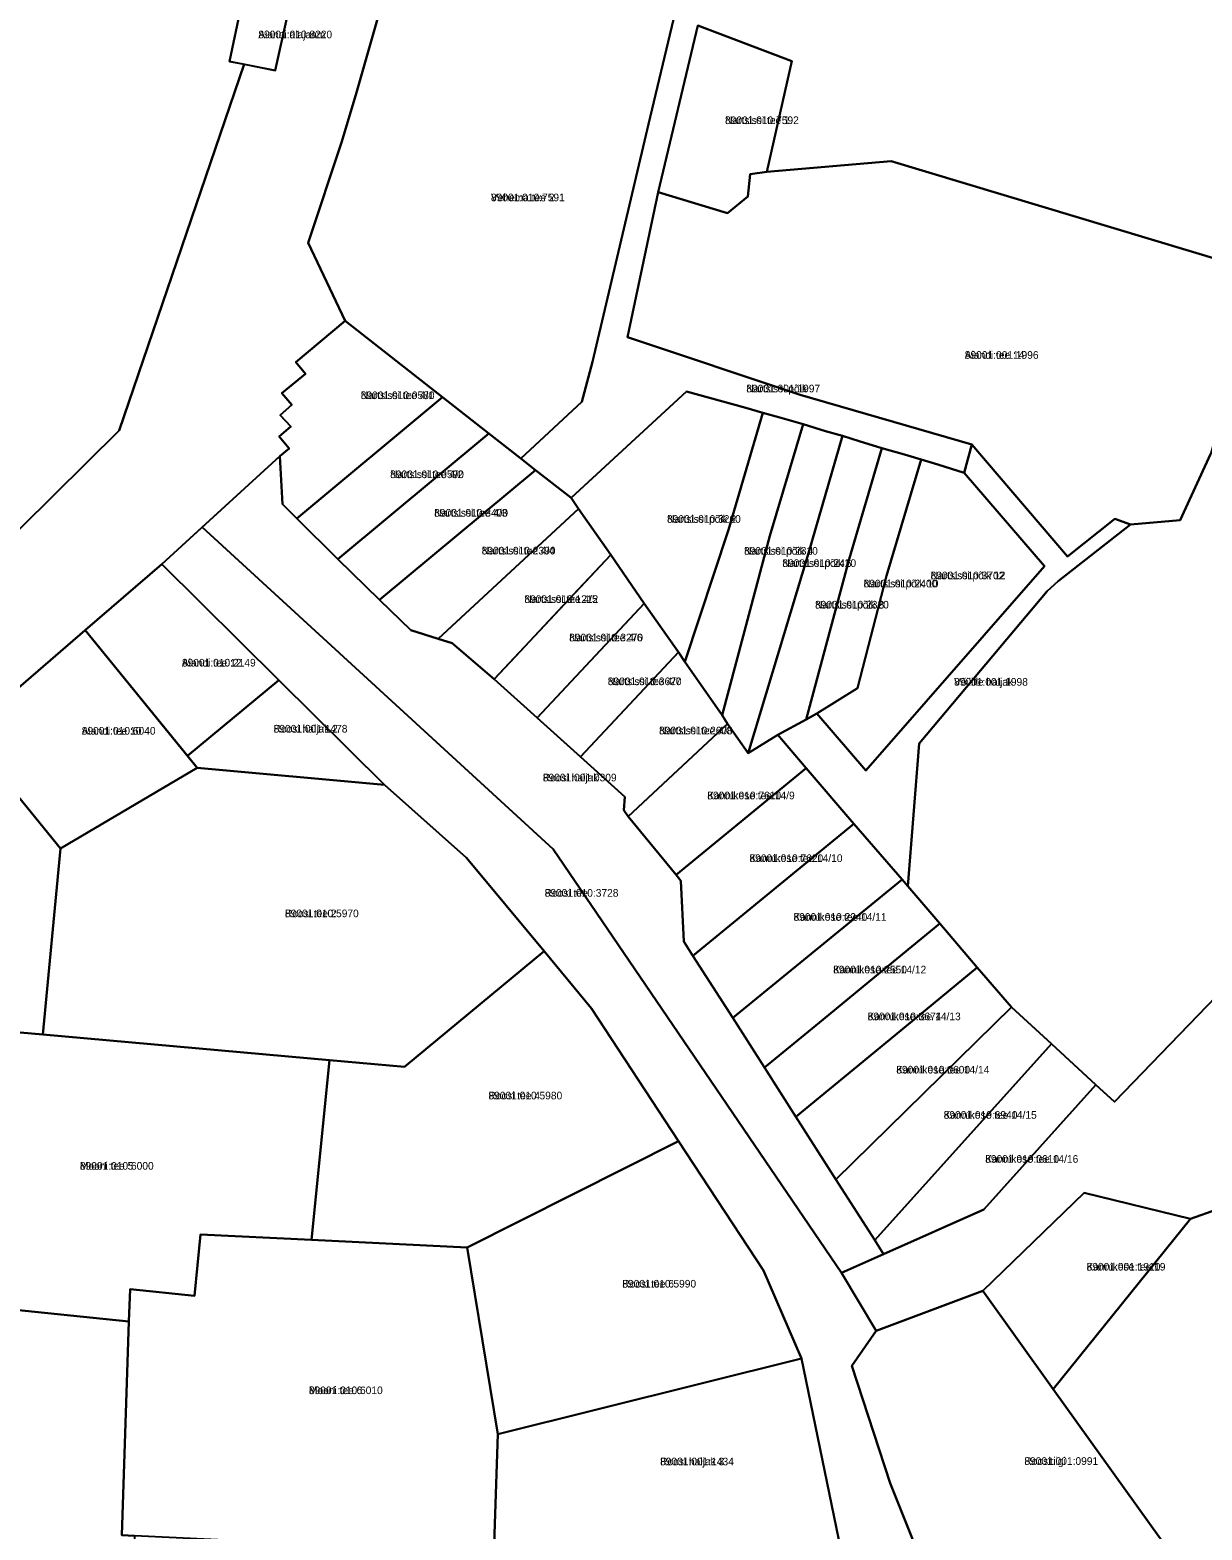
# Model space of a CAD drawing. Extents: x 526849 to 562296, y 6591741 to 6618546.
# Drawn here: x 547477.1 to 547707.4, y 6596107.7 to 6596402.5 of the extents above; entities that cross this region are included whole.
import ezdxf

# ---------------------------------------------------------------- set-up
doc = ezdxf.new("R2010")
doc.units = 0
for name, color, linetype in [('L_AADRESS', 7, 'Continuous'), ('PIIR', 7, 'Continuous'), ('TUNNUS', 7, 'Continuous')]:
    doc.layers.add(name, color=color, linetype=linetype)

msp = doc.modelspace()

# ---------------------------------------------------------------- linework, layer by layer
at = {"layer": 'PIIR'}
for points in [[(547547.94, 6596413.68), (547541.27, 6596390.17), (547538.35, 6596380.55), (547531.76, 6596360.64), (547539.03, 6596345.34), (547529.29, 6596337.2), (547531.22, 6596334.92), (547526.57, 6596331.13), (547528.5, 6596328.81), (547526.21, 6596326.8), (547528.35, 6596324.59), (547526.03, 6596322.59), (547527.98, 6596320.24), (547526.19, 6596318.74), (547502.97, 6596297.54), (547487.91, 6596284.53), (547464.56, 6596264.36)], [(547436.55, 6596266.41), (547494.58, 6596323.81), (547519.19, 6596395.74), (547525.25, 6596394.54), (547527.65, 6596405.37)], [(547608.34, 6596403.39), (547600.54, 6596370.65), (547594.52, 6596342.12), (547628.42, 6596330.79), (547662.19, 6596321.02), (547660.66, 6596315.49), (547655.5, 6596317.1), (547652.19, 6596318.08), (547648.91, 6596319.06), (547644.51, 6596320.34), (547640.02, 6596321.68), (547636.77, 6596322.72), (547633.4, 6596323.68), (547629.02, 6596325.01), (547624.43, 6596326.32), (547621.1, 6596327.29), (547617.74, 6596328.27), (547606.1, 6596331.43), (547583.42, 6596310.53), (547576.41, 6596316.01), (547573.51, 6596318.28), (547585.49, 6596329.44), (547587.59, 6596337.3), (547598.61, 6596384.01), (547603.56, 6596404.56)], [(547719.05, 6596354.82), (547646.28, 6596376.7), (547621.91, 6596374.59), (547626.79, 6596396.36), (547608.34, 6596403.39)], [(547706.39, 6596096.06), (547678.12, 6596135.41), (547705.14, 6596168.88), (547751.73, 6596185.38), (547765.81, 6596222.42), (547774.28, 6596244.68), (547784.51, 6596273.18), (547786.25, 6596291.35), (547816.28, 6596354.76), (547818.08, 6596359.67), (547851.56, 6596357.26), (547867.85, 6596356.78), (547882.68, 6596357.65), (547882.59, 6596354.87), (547879.67, 6596315.25), (547878.79, 6596293.54), (547877.89, 6596271.47), (547876.9, 6596247.63), (547875.48, 6596216.32), (547874.71, 6596199.06), (547874.51, 6596195.05), (547877.57, 6596194.93), (547877.34, 6596152.04), (547875.55, 6596092.04)], [(547763.12, 6596267.42), (547690.17, 6596191.87), (547686.52, 6596195.24), (547677.79, 6596203.24), (547669.94, 6596210.45), (547663.24, 6596218.29), (547655.88, 6596226.9), (547649.56, 6596234.23), (547651.83, 6596262.3), (547676.97, 6596292.19), (547679.13, 6596294.15), (547693.33, 6596305.3), (547703.1, 6596306.18), (547709.04, 6596319.15)], [(547751.73, 6596185.38), (547705.14, 6596168.88), (547684.21, 6596173.98), (547664.3, 6596154.73), (547643.38, 6596146.88), (547636.58, 6596158.24), (547644.82, 6596161.92), (547664.55, 6596170.73), (547686.52, 6596195.24), (547690.17, 6596191.87), (547763.12, 6596267.42)]]:
    msp.add_lwpolyline(points, dxfattribs=at)
for points in [[(547558.11, 6596330.34), (547539.03, 6596345.34), (547531.76, 6596360.64), (547538.35, 6596380.55), (547541.27, 6596390.17), (547547.94, 6596413.68), (547575.43, 6596415.26), (547586.41, 6596413.51), (547603.56, 6596404.56), (547598.61, 6596384.01), (547587.59, 6596337.3), (547585.49, 6596329.44), (547573.51, 6596318.28), (547567.22, 6596323.2)], [(547416.77, 6596407.3), (547432.18, 6596406.08), (547518.58, 6596407.17), (547516.26, 6596396.32), (547519.19, 6596395.74), (547494.58, 6596323.81), (547436.55, 6596266.41), (547362.32, 6596292.91), (547414.29, 6596397.55)], [(547527.65, 6596405.37), (547525.25, 6596394.54), (547516.26, 6596396.32), (547518.58, 6596407.17)], [(547626.79, 6596396.36), (547621.91, 6596374.59), (547618.63, 6596374.15), (547618.13, 6596369.78), (547614.13, 6596366.5), (547600.54, 6596370.65), (547608.34, 6596403.39)], [(547594.52, 6596342.12), (547600.54, 6596370.65), (547614.13, 6596366.5), (547618.13, 6596369.78), (547618.63, 6596374.15), (547621.91, 6596374.59), (547646.28, 6596376.7), (547719.05, 6596354.82), (547718.25, 6596351.97), (547715.23, 6596341.14), (547712.28, 6596330.22), (547709.13, 6596319.31), (547709.04, 6596319.15), (547703.1, 6596306.18), (547693.33, 6596305.3), (547690.25, 6596306.42), (547680.99, 6596299.05), (547662.19, 6596321.02), (547628.42, 6596330.79)], [(547526.7, 6596309.3), (547526.19, 6596318.74), (547527.98, 6596320.24), (547526.03, 6596322.59), (547528.35, 6596324.59), (547526.21, 6596326.8), (547528.5, 6596328.81), (547526.57, 6596331.13), (547531.22, 6596334.92), (547529.29, 6596337.2), (547539.03, 6596345.34), (547558.11, 6596330.34), (547529.52, 6596306.51)], [(547591.19, 6596299.37), (547584.89, 6596308.42), (547583.42, 6596310.53), (547606.1, 6596331.43), (547617.74, 6596328.27), (547621.1, 6596327.29), (547614.32, 6596304.24), (547605.77, 6596278.36), (547604.49, 6596280.2), (547597.79, 6596289.82)], [(547567.22, 6596323.2), (547537.58, 6596298.52), (547529.52, 6596306.51), (547558.11, 6596330.34)], [(547605.77, 6596278.36), (547614.32, 6596304.24), (547621.1, 6596327.29), (547624.43, 6596326.32), (547629.02, 6596325.01), (547622.47, 6596303.12), (547613.08, 6596267.85)], [(547573.51, 6596318.28), (547576.41, 6596316.01), (547545.79, 6596290.52), (547537.58, 6596298.52), (547567.22, 6596323.2)], [(547614.15, 6596266.15), (547613.08, 6596267.85), (547622.47, 6596303.12), (547629.02, 6596325.01), (547633.4, 6596323.68), (547636.77, 6596322.72), (547630.08, 6596299.69), (547618.19, 6596260.36)], [(547629.59, 6596267.02), (547624.02, 6596264.01), (547618.19, 6596260.36), (547630.08, 6596299.69), (547636.77, 6596322.72), (547640.02, 6596321.68), (547644.51, 6596320.34), (547638.05, 6596298.49)], [(547660.66, 6596315.49), (547662.19, 6596321.02), (547680.99, 6596299.05), (547690.25, 6596306.42), (547693.33, 6596305.3), (547679.13, 6596294.15), (547676.97, 6596292.19), (547651.83, 6596262.3), (547649.56, 6596234.23), (547648.47, 6596235.58), (547638.97, 6596246.52), (547629.63, 6596257.45), (547624.02, 6596264.01), (547629.59, 6596267.02), (547631.69, 6596268.16), (547641.32, 6596257.01), (547676.43, 6596297.15)], [(547629.59, 6596267.02), (547638.05, 6596298.49), (547644.51, 6596320.34), (547648.91, 6596319.06), (547652.19, 6596318.08), (547645.41, 6596295.21), (547639.68, 6596273.18), (547631.69, 6596268.16)], [(547636.58, 6596158.24), (547579.89, 6596241.49), (547510.9, 6596304.78), (547526.19, 6596318.74), (547526.7, 6596309.3), (547529.52, 6596306.51), (547537.58, 6596298.52), (547545.79, 6596290.52), (547551.91, 6596284.55), (547557.3, 6596282.85), (547560.03, 6596282.03), (547568.3, 6596274.91), (547576.76, 6596267.31), (547585.29, 6596259.64), (547594, 6596251.81), (547593.8, 6596249.16), (547594.63, 6596247.97), (547604.04, 6596236.48), (547604.98, 6596235.33), (547605.54, 6596223.35), (547607.32, 6596220.55), (547615.18, 6596208.37), (547621.42, 6596198.64), (547627.61, 6596188.92), (547635.47, 6596176.59), (547643.07, 6596164.66), (547644.82, 6596161.92)], [(547652.19, 6596318.08), (547655.5, 6596317.1), (547660.66, 6596315.49), (547676.43, 6596297.15), (547641.32, 6596257.01), (547631.69, 6596268.16), (547639.68, 6596273.18), (547645.41, 6596295.21)], [(547583.42, 6596310.53), (547584.89, 6596308.42), (547557.3, 6596282.85), (547551.91, 6596284.55), (547545.79, 6596290.52), (547576.41, 6596316.01)], [(547584.89, 6596308.42), (547591.19, 6596299.37), (547582.64, 6596290.24), (547572.5, 6596279.4), (547568.3, 6596274.91), (547560.03, 6596282.03), (547557.3, 6596282.85)], [(547502.97, 6596297.54), (547510.9, 6596304.78), (547579.89, 6596241.49), (547636.58, 6596158.24), (547643.38, 6596146.88), (547638.59, 6596140), (547646.1, 6596116.96), (547653.47, 6596098.6), (547644.16, 6596099.09), (547637.32, 6596099.45), (547628.66, 6596141.44), (547621.22, 6596158.7), (547604.53, 6596184.16), (547587.45, 6596210.21), (547578.09, 6596221.49), (547562.86, 6596239.84), (547546.73, 6596254.13), (547525.95, 6596274.75)], [(547568.3, 6596274.91), (547591.19, 6596299.37), (547597.79, 6596289.82), (547576.76, 6596267.31)], [(547502.97, 6596297.54), (547525.95, 6596274.75), (547508.05, 6596259.84), (547487.91, 6596284.53)], [(547576.76, 6596267.31), (547597.79, 6596289.82), (547604.49, 6596280.2), (547585.29, 6596259.64)], [(547509.93, 6596257.53), (547483.08, 6596241.65), (547464.56, 6596264.36), (547487.91, 6596284.53)], [(547605.77, 6596278.36), (547613.08, 6596267.85), (547614.15, 6596266.15), (547594.63, 6596247.97), (547593.8, 6596249.16), (547594, 6596251.81), (547585.29, 6596259.64), (547604.49, 6596280.2)], [(547508.05, 6596259.84), (547525.95, 6596274.75), (547546.73, 6596254.13), (547509.93, 6596257.53)], [(547618.19, 6596260.36), (547624.02, 6596264.01), (547629.63, 6596257.45), (547604.04, 6596236.48), (547594.63, 6596247.97), (547614.15, 6596266.15)], [(547464.56, 6596264.36), (547483.08, 6596241.65), (547479.59, 6596205.09), (547465.46, 6596206.34), (547437.32, 6596240.84)], [(547562.86, 6596239.84), (547578.09, 6596221.49), (547550.7, 6596198.77), (547535.96, 6596200.08), (547479.59, 6596205.09), (547483.08, 6596241.65), (547509.93, 6596257.53), (547546.73, 6596254.13)], [(547605.54, 6596223.35), (547604.98, 6596235.33), (547604.04, 6596236.48), (547629.63, 6596257.45), (547638.97, 6596246.52), (547607.32, 6596220.55)], [(547638.97, 6596246.52), (547648.47, 6596235.58), (547615.18, 6596208.37), (547607.32, 6596220.55)], [(547615.18, 6596208.37), (547648.47, 6596235.58), (547649.56, 6596234.23), (547655.88, 6596226.9), (547641.94, 6596215.47), (547632.92, 6596208.07), (547621.42, 6596198.64)], [(547621.42, 6596198.64), (547632.92, 6596208.07), (547641.94, 6596215.47), (547655.88, 6596226.9), (547663.24, 6596218.29), (547650.43, 6596207.73), (547638.97, 6596198.29), (547627.61, 6596188.92)], [(547532.41, 6596164.75), (547535.96, 6596200.08), (547550.7, 6596198.77), (547578.09, 6596221.49), (547587.45, 6596210.21), (547604.53, 6596184.16), (547563.01, 6596163.24)], [(547635.47, 6596176.59), (547627.61, 6596188.92), (547638.97, 6596198.29), (547650.43, 6596207.73), (547663.24, 6596218.29), (547669.94, 6596210.45)], [(547635.47, 6596176.59), (547669.94, 6596210.45), (547677.79, 6596203.24), (547643.07, 6596164.66)], [(547437.6, 6596154.79), (547440.01, 6596178.32), (547438.61, 6596184.25), (547438.73, 6596191.13), (547442.64, 6596200.1), (547442.55, 6596208.38), (547465.46, 6596206.34), (547479.59, 6596205.09), (547535.96, 6596200.08), (547532.41, 6596164.75), (547510.61, 6596165.82), (547509.4, 6596153.78), (547496.75, 6596155.08), (547496.53, 6596148.71), (547445.48, 6596153.98)], [(547686.52, 6596195.24), (547664.55, 6596170.73), (547644.82, 6596161.92), (547643.07, 6596164.66), (547677.79, 6596203.24)], [(547563.01, 6596163.24), (547604.53, 6596184.16), (547621.22, 6596158.7), (547628.66, 6596141.44), (547569.02, 6596126.6)], [(547678.12, 6596135.41), (547664.3, 6596154.73), (547684.21, 6596173.98), (547705.14, 6596168.88)], [(547496.53, 6596148.71), (547496.75, 6596155.08), (547509.4, 6596153.78), (547510.61, 6596165.82), (547532.41, 6596164.75), (547563.01, 6596163.24), (547569.02, 6596126.6), (547568.22, 6596103.06), (547563.12, 6596103.32), (547546.75, 6596104.11), (547530.38, 6596104.94), (547513.97, 6596105.78), (547497.6, 6596106.6), (547495.1, 6596106.73)], [(547664.3, 6596154.73), (547678.12, 6596135.41), (547706.39, 6596096.06), (547688.29, 6596096.92), (547675.94, 6596097.66), (547660.04, 6596098.26), (547653.47, 6596098.6), (547646.1, 6596116.96), (547638.59, 6596140), (547643.38, 6596146.88)], [(547270.52, 6596117.43), (547316.37, 6596071.96), (547361.8, 6596108.26), (547443.86, 6596105.58), (547445.48, 6596153.98), (547496.53, 6596148.71), (547495.1, 6596106.73), (547497.6, 6596106.6), (547497.04, 6596090.99), (547492.97, 6596090.65), (547490.86, 6596041.33), (547490.66, 6596035.68), (547488.51, 6595983.56), (547492.72, 6595983.52), (547492.6, 6595979.92), (547491.98, 6595964.43), (547491.76, 6595958.44), (547232.4, 6596069.31), (547228.78, 6596080.54)], [(547628.66, 6596141.44), (547637.32, 6596099.45), (547628.31, 6596099.92), (547612.01, 6596100.77), (547595.64, 6596101.63), (547579.51, 6596102.47), (547568.22, 6596103.06), (547569.02, 6596126.6)]]:
    msp.add_lwpolyline(points, close=True, dxfattribs=at)

# ---------------------------------------------------------------- texts
at = {"layer": 'L_AADRESS'}
for s, p in [('Aiandi alajaam', (547521.95, 6596400.85)), ('Nartsissi tee 1', (547613.66, 6596384)), ('Vehema tee 2', (547567.66, 6596368.83)), ('Aiandi tee 14', (547660.78, 6596337.88)), ('Nartsissi tee 4/1', (547542.07, 6596329.96)), ('Nartsissi põik', (547617.85, 6596331.28)), ('Nartsissi tee 4/2', (547547.85, 6596314.43)), ('Nartsissi tee 4/3', (547556.51, 6596306.86)), ('Nartsissi põik 2', (547602.26, 6596305.65)), ('Nartsissi tee 4/4', (547565.84, 6596299.43)), ('Nartsissi põik 4', (547617.4, 6596299.38)), ('Nartsissi põik 6', (547624.93, 6596296.98)), ('Nartsissi põik 12', (547654.06, 6596294.55)), ('Nartsissi põik 10', (547640.89, 6596292.96)), ('Nartsissi tee 4/5', (547574.24, 6596289.91)), ('Nartsissi põik 8', (547631.35, 6596288.81)), ('Nartsissi tee 4/6', (547583.04, 6596282.35)), ('Aiandi tee 12', (547506.93, 6596277.41)), ('Nartsissi tee 4/7', (547590.62, 6596273.75)), ('Võilille haljak', (547658.68, 6596273.64)), ('Aiandi tee 10', (547487.25, 6596264.03)), ('Roosi haljak 2', (547524.96, 6596264.44)), ('Nartsissi tee 4/8', (547600.69, 6596264.08)), ('Roosi haljak', (547577.86, 6596254.84)), ('Kannikese tee 14/9', (547610.18, 6596251.32)), ('Kannikese tee 14/10', (547618.46, 6596239)), ('Roosi tee', (547578.22, 6596232.18)), ('Roosi tee 2', (547527.18, 6596228.15)), ('Kannikese tee 14/11', (547627.12, 6596227.45)), ('Kannikese tee 14/12', (547634.91, 6596217.11)), ('Kannikese tee 14/13', (547641.69, 6596207.91)), ('Kannikese tee 14/14', (547647.32, 6596197.44)), ('Roosi tee 4', (547567.17, 6596192.36)), ('Kannikese tee 14/15', (547656.63, 6596188.55)), ('Kannikese tee 14/16', (547664.8, 6596179.9)), ('Mooni tee 5', (547486.88, 6596178.54)), ('Kannikese tee 19', (547684.72, 6596158.72)), ('Roosi tee 6', (547593.48, 6596155.38)), ('Mooni tee 6', (547531.89, 6596134.44)), ('Roosi haljak 3', (547600.9, 6596120.45)), ('Roositiigi', (547672.49, 6596120.54))]:
    msp.add_text(s, height=1.5, dxfattribs=at).set_placement(p)
at = {"layer": 'TUNNUS'}
for s, p in [('89001:010:8220', (547521.95, 6596400.85)), ('89001:010:7592', (547613.66, 6596384)), ('89001:010:7591', (547567.66, 6596368.83)), ('89001:001:1996', (547660.78, 6596337.88)), ('89001:010:0580', (547542.07, 6596329.96)), ('89001:001:1997', (547617.85, 6596331.28)), ('89001:010:0590', (547547.85, 6596314.43)), ('89001:010:8400', (547556.51, 6596306.86)), ('89001:010:3260', (547602.26, 6596305.65)), ('89001:010:2390', (547565.84, 6596299.43)), ('89001:010:2310', (547617.4, 6596299.38)), ('89001:010:2420', (547624.93, 6596296.98)), ('89001:010:3702', (547654.06, 6596294.55)), ('89001:010:2400', (547640.89, 6596292.96)), ('89001:010:1212', (547574.24, 6596289.91)), ('89001:010:2320', (547631.35, 6596288.81)), ('89001:010:3270', (547583.04, 6596282.35)), ('89001:010:2149', (547506.93, 6596277.41)), ('89001:010:3620', (547590.62, 6596273.75)), ('89001:001:1998', (547658.68, 6596273.64)), ('89001:010:6040', (547487.25, 6596264.03)), ('89001:001:1478', (547524.96, 6596264.44)), ('89001:010:2600', (547600.69, 6596264.08)), ('89001:001:0309', (547577.86, 6596254.84)), ('89001:010:7610', (547610.18, 6596251.32)), ('89001:010:7620', (547618.46, 6596239)), ('89001:010:3728', (547578.22, 6596232.18)), ('89001:010:5970', (547527.18, 6596228.15)), ('89001:010:2240', (547627.12, 6596227.45)), ('89001:010:2550', (547634.91, 6596217.11)), ('89001:010:3674', (547641.69, 6596207.91)), ('89001:010:0600', (547647.32, 6596197.44)), ('89001:010:5980', (547567.17, 6596192.36)), ('89001:010:6940', (547656.63, 6596188.55)), ('89001:010:0610', (547664.8, 6596179.9)), ('89001:010:6000', (547486.88, 6596178.54)), ('89001:001:1910', (547684.72, 6596158.72)), ('89001:010:5990', (547593.48, 6596155.38)), ('89001:010:6010', (547531.89, 6596134.44)), ('89001:001:1434', (547600.9, 6596120.45)), ('89001:001:0991', (547672.49, 6596120.54))]:
    msp.add_text(s, height=1.5, dxfattribs=at).set_placement(p)

doc.saveas('drawing.dxf')
